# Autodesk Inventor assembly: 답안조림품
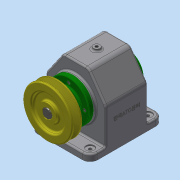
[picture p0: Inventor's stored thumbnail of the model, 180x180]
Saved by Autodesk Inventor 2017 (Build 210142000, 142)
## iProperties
Part Number: 답안조림품
Material: 일반
Document SubType Name: Assembly
Designer: MRC
Author: MRC
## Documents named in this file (15)
- C:\Users\MRC\Desktop\721206V1008\답안조림품.iam
- C:\Users\MRC\Desktop\721206V1008\본체.ipt
- C:\Users\MRC\Desktop\721206V1008\축.ipt
- C:\Users\MRC\Desktop\721206V1008\뒤커버.ipt
- C:\Users\MRC\Desktop\721206V1008\베어링 6203.ipt
- C:\Users\MRC\Desktop\721206V1008\칼라.ipt
- C:\Users\MRC\Desktop\721206V1008\키 - 6 x 6 x 22.ipt
- C:\Users\MRC\Desktop\721206V1008\스퍼기어.ipt
- C:\Users\MRC\Desktop\721206V1008\키 - 5 x 5 x 18.ipt
- C:\Users\MRC\Desktop\721206V1008\오일 실 17 x 32 x 8.ipt
- C:\Users\MRC\Desktop\721206V1008\앞커버.ipt
- C:\Users\MRC\Desktop\721206V1008\멈춤나사 - M4x10.ipt
- C:\Users\MRC\Desktop\721206V1008\볼트 M3 x 8.ipt
- C:\Users\MRC\Desktop\721206V1008\볼트 M3 x 10.ipt
- C:\Users\MRC\Desktop\721206V1008\V-벨트풀리.ipt
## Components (9 placed, 3 different names)
1. ISO 4762 M3 x 8:1
2. ISO 4762 M3 x 8:2
3. ISO 4762 M3 x 8:3
4. ISO 4762 M3 x 8:4
5. ISO 4762 M3 x 10:1
6. ISO 4762 M3 x 10:2
7. ISO 4762 M3 x 10:3
8. ISO 4762 M3 x 10:4
9. V-벨트풀리:1
